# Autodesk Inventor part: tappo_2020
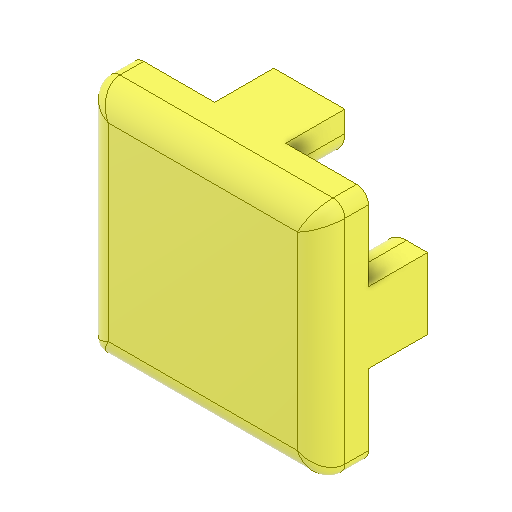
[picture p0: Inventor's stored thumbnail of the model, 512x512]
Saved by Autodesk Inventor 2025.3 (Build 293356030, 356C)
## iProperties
Created: 2025-09
Part Number: tappo_2020
Material: Plastica ABS
Document SubType Name: Modeling
Designer: Ryzen5700u
Density: 1.06 g/cm^3
Appearance: Liscia - Giallo
Author: Ryzen5700u
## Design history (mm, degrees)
sketch "Schizzo1"
  geometry: L1 (-10, 10)-(10, 10); L2 (10, 10)-(10, -10); L3 (10, -10)-(-10, -10); L4 (-10, -10)-(-10, 10); L5 (-10, 10)-(10, -10); L6 (10, 10)-(-10, -10); 1 further point
  constraints: 12 end point, 2 midpoint, 2 parallel, 1 horizontal, 1 perpendicular
  dimensions: "d0" = 20 distance of L2.end L3.end; "d1" = 20 distance of L1.end L2.end
extrude "Estrusione1" new body sketch "Schizzo1" distance "d2" = 4; taper "d3" = 0 deg
sketch "Schizzo2"
  geometry: L1 (10, -10)-(-10, -10) reference; L2 (10, 10)-(10, -10) reference; L3 (-10, 10)-(10, 10) reference; L4 (-10, -10)-(-10, 10) reference; L5 (8, 3)-(9.7, 3) reference; L6 (9.7, -3)-(8, -3) reference; L7 (10, -3)-(6.213, -3); L8 (6.213, -3)-(6.213, 3); L9 (6.213, 3)-(10, 3); L10 (10, 3)-(10, -3); 6 further points
  constraints: 8 end point, 2 parallel, 1 horizontal, 1 perpendicular, 1 point on line
extrude "Estrusione2" join sketch "Schizzo2" distance "d4" = 5; taper "d5" = 0 deg
fillet "Raccordo1" dims "d6" = 2
pattern_circular "Serie circolare1" dims "d8" = 360 deg
fillet "Raccordo2" dims "d10" = 1
fillet "Raccordo3" dims "d11" = 2
node "Solido1"
node "Linea chiusa proiettata1"
node "Riferimento1"
node "Riferimento2"
